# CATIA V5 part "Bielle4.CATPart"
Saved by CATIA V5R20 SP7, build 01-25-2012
Part number: Bielle4
Bounding box of the stored display mesh (mm): x 10 to 15, y -5.969 to 16.003, z 117.592 to 157.997
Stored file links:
  J:\ACHTUNG2\Bielle4.CATPart
  J:\ACHTUNG2\cmilovidof.CATProduct
  J:\ACHTUNG\IAO non optimisé fini et qui marche à rendre\Bielle4.CATPart
  J:\ACHTUNG2\Bielle5.CATPart
  J:\ACHTUNG2\skl_Equerre6.CATPart
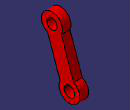
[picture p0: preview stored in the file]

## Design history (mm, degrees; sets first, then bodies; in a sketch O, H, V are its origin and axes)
External parameters (linked from other documents)
  External.diam_roue = 64 mm
Set1
  Plane1: linked copy from another document
  Line1 "Axe_Bielle4Levier1": linked copy from another document
  Line2 "Axe_Bielle4Equerre6": linked copy from another document
  Sketch1, origin (5, 0, 0), H (0, 1, 0), V (0, 0, 1), geometry linked from another document
  Plane2: linked copy from another document
  Plane3: linked copy from another document
  Line3: linked copy from another document
Body1 (main body)
  Sketch2 on Plane3, origin (10, 0, 0), H (0, 1, 0), V (0, 0, 1)
    point P1 (0, 152)
    point P2 (0, 152)
    construction circle A1 centre (10.0334, 123.5885) radius 6
    point P3 (12.4733, 129.07)
    construction circle A2 centre (0, 152) radius 6
    point P4 (5.3619, 149.3075)
    point P5 (12.4733, 129.07)
    point P6 (-2.4443, 146.5205)
    point P7 (-2.4443, 146.5205)
    point P8 (5.3619, 149.3075)
    line L1 (4.6693, 126.2767) -> (-2.4443, 146.5205)
    line L2 (12.4733, 129.07) -> (5.3619, 149.3075)
    arc A3 centre (10.0334, 123.5885) radius 6 from (4.6693, 126.2767) to (12.4733, 129.07) ccw
    arc A4 centre (0, 152) radius 6 from (5.3619, 149.3075) to (-2.4443, 146.5205) ccw
    reference projected point E1 (0, 152) from Line1
    circle A5 centre (0, 152) radius 3
    circle A6 centre (10.0334, 123.5885) radius 3
    reference projected point E2 (10.0334, 123.5885) from Line3
    radius A3 = 6 {= 6*External.diam_roue /64}
    radius A4 = 6 {= 6*External.diam_roue /64}
    radius A5 = 3 {= 3*External.diam_roue /64}
    radius A6 = 3 {= 3*External.diam_roue /64}
    coincidence: P2 P1, P3 A1, P4 A2, P5 A1, P6 A2, P7 A2, P3 P5, P4 P8, P6 P7
    parallelism: L2 L1
    concentricity: A2 E1, A6 A1, E2 A3
  Pad1: profile Sketch2, direction (1, 0, 0), length 5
